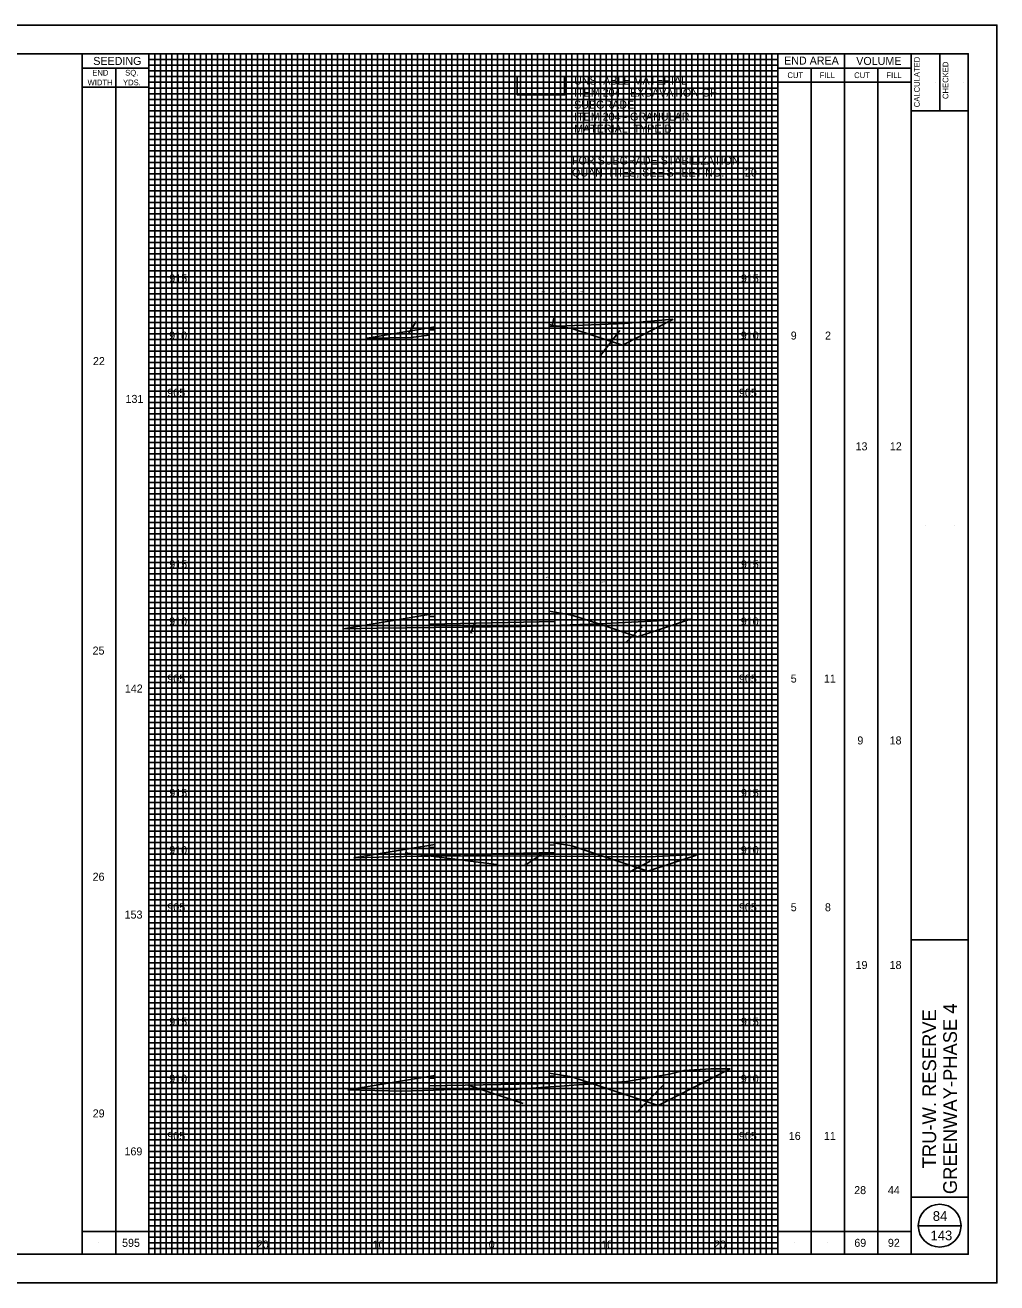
# Model space of a CAD drawing. Extents: x -73 to 160, y -2 to 1877.
# Drawn here: x 75 to 160, y 1147.5 to 1257.5 of the extents above; entities that cross this region are included whole.
import ezdxf

# ---------------------------------------------------------------- set-up
doc = ezdxf.new("R2010")
doc.units = 0
for name, color, linetype in [('DR_P_Flood_Boundary', 7, 'Continuous'), ('GK_Cells', 7, 'Continuous'), ('PV_P_EOP', 7, 'Continuous'), ('RD_X_Fence', 7, 'Continuous'), ('TX_X_5', 7, 'Continuous'), ('UT_P_Water_Cells', 7, 'Continuous'), ('XS_P_Pavt_Layers', 7, 'Continuous'), ('XS_P_Pavt_Surface', 7, 'Continuous'), ('XS_P_Special_Benching', 7, 'Continuous'), ('XS_X_Ground_Line', 7, 'Continuous')]:
    doc.layers.add(name, color=color, linetype=linetype)

msp = doc.modelspace()

# ---------------------------------------------------------------- linework, layer by layer
at = {"layer": 'DR_P_Flood_Boundary'}
for p, q in [((90.83, 1150), (90.83, 1255)), ((95.83, 1150), (95.83, 1255)), ((100.83, 1150), (100.83, 1255)), ((105.83, 1150), (105.83, 1255)), ((110.83, 1150), (110.83, 1255)), ((115.83, 1150), (115.83, 1255)), ((120.83, 1150), (120.83, 1255)), ((125.83, 1150), (125.83, 1255)), ((130.83, 1150), (130.83, 1255)), ((135.83, 1150), (135.83, 1255)), ((85.83, 1250), (140.83, 1250)), ((85.83, 1245), (140.83, 1245)), ((85.83, 1240), (140.83, 1240)), ((85.83, 1235), (140.83, 1235)), ((85.83, 1230), (140.83, 1230)), ((85.83, 1225), (140.83, 1225)), ((85.83, 1220), (140.83, 1220)), ((85.83, 1215), (140.83, 1215)), ((85.83, 1210), (140.83, 1210)), ((85.83, 1205), (140.83, 1205)), ((85.83, 1200), (140.83, 1200)), ((85.83, 1195), (140.83, 1195)), ((85.83, 1190), (140.83, 1190)), ((85.83, 1185), (140.83, 1185)), ((85.83, 1180), (140.83, 1180)), ((85.83, 1175), (140.83, 1175)), ((85.83, 1170), (140.83, 1170)), ((85.83, 1165), (140.83, 1165)), ((85.83, 1160), (140.83, 1160)), ((85.83, 1155), (140.83, 1155))]:
    msp.add_line(p, q, dxfattribs=at)
at = {"layer": 'GK_Cells'}
for p, q in [((152.5, 1150), (152.5, 1255)), ((155, 1255), (155, 1250)), ((152.5, 1250), (157.5, 1250)), ((152.5, 1177.5), (157.5, 1177.5)), ((152.5, 1155), (157.5, 1155))]:
    msp.add_line(p, q, dxfattribs=at)
msp.add_lwpolyline([(0, 1255), (157.5, 1255), (157.5, 1150), (0, 1150)], close=True, dxfattribs=at)
at = {"layer": 'PV_P_EOP'}
msp.add_lwpolyline([(118.05, 1253.02), (122.19, 1253.02), (122.19, 1251.4), (118.05, 1251.4)], close=True, dxfattribs=at)
msp.add_lwpolyline([(118.05, 1251.4), (122.19, 1251.4), (122.19, 1253.02), (118.05, 1253.02), (118.05, 1251.4)], dxfattribs=at)
at = {"layer": 'RD_X_Fence'}
for p, q in [((110.83, 1231.11), (104.92, 1230.12)), ((108.54, 1230.49), (109.21, 1231.59)), ((120.83, 1231.31), (120.83, 1231.2)), ((121.6, 1231.18), (120.83, 1231.31)), ((120.83, 1231.15), (121.6, 1231.18)), ((121.09, 1231.21), (121.25, 1231.86)), ((121.6, 1231.18), (122.83, 1230.97)), ((122.83, 1230.97), (127.25, 1229.5)), ((127.25, 1229.5), (131.67, 1231.75)), ((110.33, 1230.85), (110.83, 1230.86)), ((110.33, 1230.4), (110.33, 1230.85)), ((127.01, 1230.79), (125.34, 1228.6)), ((110.83, 1206.04), (102.84, 1204.71)), ((110.33, 1205.78), (110.83, 1205.79)), ((110.33, 1205.12), (110.33, 1205.78)), ((122.83, 1205.91), (120.83, 1206.24)), ((120.83, 1205.99), (121.33, 1206)), ((121.33, 1206), (121.33, 1205.34)), ((125.18, 1205.13), (122.83, 1205.91)), ((121.33, 1205.34), (110.33, 1205.12)), ((114.3, 1205.21), (113.98, 1204.33)), ((133.19, 1205.54), (125.18, 1205.13)), ((125.18, 1205.13), (128.56, 1204)), ((128.98, 1204.89), (127.6, 1203.55)), ((128.56, 1204), (133.19, 1205.54)), ((110.83, 1185.84), (103.76, 1184.67)), ((122.83, 1185.71), (120.83, 1186.04)), ((120.83, 1185.79), (121.33, 1185.8)), ((121.33, 1185.8), (121.33, 1185.14)), ((108.25, 1185.11), (116.23, 1184.09)), ((110.33, 1185.58), (110.83, 1185.59)), ((110.33, 1184.92), (110.33, 1185.58)), ((121.33, 1185.14), (110.33, 1184.92)), ((120.36, 1185.12), (118.83, 1184.08)), ((125.62, 1184.78), (122.83, 1185.71)), ((125.62, 1184.78), (129.46, 1183.5)), ((129.46, 1183.5), (133.72, 1184.92)), ((129.66, 1184.38), (127.83, 1183.43)), ((130.36, 1163), (136.68, 1166.22)), ((110.83, 1165.64), (103.24, 1164.38)), ((110.33, 1165.38), (110.83, 1165.39)), ((110.33, 1164.72), (110.33, 1165.38)), ((121.33, 1164.94), (110.33, 1164.72)), ((122.83, 1165.51), (120.83, 1165.84)), ((120.83, 1165.59), (121.33, 1165.6)), ((121.33, 1165.6), (121.33, 1164.94)), ((124.67, 1164.9), (122.83, 1165.51)), ((113.74, 1164.78), (118.57, 1163.2)), ((124.67, 1164.9), (130.36, 1163)), ((130.82, 1164.78), (128.5, 1162.42))]:
    msp.add_line(p, q, dxfattribs=at)
for points in [[(110.83, 1230.86), (110.83, 1231), (110.83, 1231.11)], [(120.83, 1231.2), (120.83, 1231.15)], [(131.66, 1231.79), (127.46, 1231.4), (121.6, 1231.18)], [(131.67, 1231.75), (131.66, 1231.79)], [(104.92, 1230.12), (108.74, 1230.18), (110.33, 1230.4)], [(110.83, 1205.79), (110.83, 1205.94), (110.83, 1206.04)], [(120.83, 1206.24), (120.83, 1206.14), (120.83, 1205.99)], [(102.84, 1204.71), (105.79, 1204.75), (115.83, 1204.87), (118.47, 1204.9), (125.18, 1205.13)], [(133.19, 1205.54), (133.19, 1205.54)], [(110.83, 1185.59), (110.83, 1185.74), (110.83, 1185.84)], [(120.83, 1186.04), (120.83, 1185.94), (120.83, 1185.79)], [(103.76, 1184.67), (108.13, 1184.8), (110.33, 1184.82)], [(110.33, 1184.92), (110.33, 1184.82)], [(110.33, 1184.82), (110.33, 1184.92)], [(110.33, 1184.82), (113.35, 1184.86), (115.83, 1184.84), (125.62, 1184.78)], [(133.71, 1184.97), (129.55, 1184.76), (125.62, 1184.78)], [(133.72, 1184.92), (133.71, 1184.97)], [(136.68, 1166.22), (134.97, 1166.23), (132.62, 1166.06), (131.37, 1165.76), (127.6, 1165.1), (124.67, 1164.9)], [(110.83, 1165.39), (110.83, 1165.54), (110.83, 1165.64)], [(120.83, 1165.84), (120.83, 1165.74), (120.83, 1165.59)], [(103.24, 1164.38), (107.95, 1164.26), (112.55, 1164.4), (115.83, 1164.38), (117.21, 1164.38), (124.67, 1164.9)]]:
    msp.add_lwpolyline(points, dxfattribs=at)
at = {"layer": 'TX_X_5'}
msp.add_lwpolyline([(-10, 1147.5), (160, 1147.5), (160, 1257.5), (-10, 1257.5)], close=True, dxfattribs=at)
at = {"layer": 'UT_P_Water_Cells'}
for p, q in [((85.83, 1254.5), (140.83, 1254.5)), ((85.83, 1254), (140.83, 1254)), ((86.33, 1150), (86.33, 1255)), ((86.83, 1150), (86.83, 1255)), ((87.33, 1150), (87.33, 1255)), ((87.83, 1150), (87.83, 1255)), ((88.33, 1150), (88.33, 1255)), ((88.83, 1150), (88.83, 1255)), ((89.33, 1150), (89.33, 1255)), ((89.83, 1150), (89.83, 1255)), ((90.33, 1150), (90.33, 1255)), ((91.33, 1150), (91.33, 1255)), ((91.83, 1150), (91.83, 1255)), ((92.33, 1150), (92.33, 1255)), ((92.83, 1150), (92.83, 1255)), ((93.33, 1150), (93.33, 1255)), ((93.83, 1150), (93.83, 1255)), ((94.33, 1150), (94.33, 1255)), ((94.83, 1150), (94.83, 1255)), ((95.33, 1150), (95.33, 1255)), ((96.33, 1150), (96.33, 1255)), ((96.83, 1150), (96.83, 1255)), ((97.33, 1150), (97.33, 1255)), ((97.83, 1150), (97.83, 1255)), ((98.33, 1150), (98.33, 1255)), ((98.83, 1150), (98.83, 1255)), ((99.33, 1150), (99.33, 1255)), ((99.83, 1150), (99.83, 1255)), ((100.33, 1150), (100.33, 1255)), ((101.33, 1150), (101.33, 1255)), ((101.83, 1150), (101.83, 1255)), ((102.33, 1150), (102.33, 1255)), ((102.83, 1150), (102.83, 1255)), ((103.33, 1150), (103.33, 1255)), ((103.83, 1150), (103.83, 1255)), ((104.33, 1150), (104.33, 1255)), ((104.83, 1150), (104.83, 1255)), ((105.33, 1150), (105.33, 1255)), ((106.33, 1150), (106.33, 1255)), ((106.83, 1150), (106.83, 1255)), ((107.33, 1150), (107.33, 1255)), ((107.83, 1150), (107.83, 1255)), ((108.33, 1150), (108.33, 1255)), ((108.83, 1150), (108.83, 1255)), ((109.33, 1150), (109.33, 1255)), ((109.83, 1150), (109.83, 1255)), ((110.33, 1150), (110.33, 1255)), ((111.33, 1150), (111.33, 1255)), ((111.83, 1150), (111.83, 1255)), ((112.33, 1150), (112.33, 1255)), ((112.83, 1150), (112.83, 1255)), ((113.33, 1150), (113.33, 1255)), ((113.83, 1150), (113.83, 1255)), ((114.33, 1150), (114.33, 1255)), ((114.83, 1150), (114.83, 1255)), ((115.33, 1150), (115.33, 1255)), ((116.33, 1150), (116.33, 1255)), ((116.83, 1150), (116.83, 1255)), ((117.33, 1150), (117.33, 1255)), ((117.83, 1150), (117.83, 1255)), ((118.33, 1150), (118.33, 1255)), ((118.83, 1150), (118.83, 1255)), ((119.33, 1150), (119.33, 1255)), ((119.83, 1150), (119.83, 1255)), ((120.33, 1150), (120.33, 1255)), ((121.33, 1150), (121.33, 1255)), ((121.83, 1150), (121.83, 1255)), ((122.33, 1150), (122.33, 1255)), ((122.83, 1150), (122.83, 1255)), ((123.33, 1150), (123.33, 1255)), ((123.83, 1150), (123.83, 1255)), ((124.33, 1150), (124.33, 1255)), ((124.83, 1150), (124.83, 1255)), ((125.33, 1150), (125.33, 1255)), ((126.33, 1150), (126.33, 1255)), ((126.83, 1150), (126.83, 1255)), ((127.33, 1150), (127.33, 1255)), ((127.83, 1150), (127.83, 1255)), ((128.33, 1150), (128.33, 1255)), ((128.83, 1150), (128.83, 1255)), ((129.33, 1150), (129.33, 1255)), ((129.83, 1150), (129.83, 1255)), ((130.33, 1150), (130.33, 1255)), ((131.33, 1150), (131.33, 1255)), ((131.83, 1150), (131.83, 1255)), ((132.33, 1150), (132.33, 1255)), ((132.83, 1150), (132.83, 1255)), ((133.33, 1150), (133.33, 1255)), ((133.83, 1150), (133.83, 1255)), ((134.33, 1150), (134.33, 1255)), ((134.83, 1150), (134.83, 1255)), ((135.33, 1150), (135.33, 1255)), ((136.33, 1150), (136.33, 1255)), ((136.83, 1150), (136.83, 1255)), ((137.33, 1150), (137.33, 1255)), ((137.83, 1150), (137.83, 1255)), ((138.33, 1150), (138.33, 1255)), ((138.83, 1150), (138.83, 1255)), ((139.33, 1150), (139.33, 1255)), ((139.83, 1150), (139.83, 1255)), ((140.33, 1150), (140.33, 1255)), ((85.83, 1253.5), (140.83, 1253.5)), ((85.83, 1253), (140.83, 1253)), ((85.83, 1252.5), (140.83, 1252.5)), ((85.83, 1252), (140.83, 1252)), ((85.83, 1251.5), (140.83, 1251.5)), ((85.83, 1251), (140.83, 1251)), ((85.83, 1250.5), (140.83, 1250.5)), ((85.83, 1249.5), (140.83, 1249.5)), ((85.83, 1249), (140.83, 1249)), ((85.83, 1248.5), (140.83, 1248.5)), ((85.83, 1248), (140.83, 1248)), ((85.83, 1247.5), (140.83, 1247.5)), ((85.83, 1247), (140.83, 1247)), ((85.83, 1246.5), (140.83, 1246.5)), ((85.83, 1246), (140.83, 1246)), ((85.83, 1245.5), (140.83, 1245.5)), ((85.83, 1244.5), (140.83, 1244.5)), ((85.83, 1244), (140.83, 1244)), ((85.83, 1243.5), (140.83, 1243.5)), ((85.83, 1243), (140.83, 1243)), ((85.83, 1242.5), (140.83, 1242.5)), ((85.83, 1242), (140.83, 1242)), ((85.83, 1241.5), (140.83, 1241.5)), ((85.83, 1241), (140.83, 1241)), ((85.83, 1240.5), (140.83, 1240.5)), ((85.83, 1239.5), (140.83, 1239.5)), ((85.83, 1239), (140.83, 1239)), ((85.83, 1238.5), (140.83, 1238.5)), ((85.83, 1238), (140.83, 1238)), ((85.83, 1237.5), (140.83, 1237.5)), ((85.83, 1237), (140.83, 1237)), ((85.83, 1236.5), (140.83, 1236.5)), ((85.83, 1236), (140.83, 1236)), ((85.83, 1235.5), (140.83, 1235.5)), ((85.83, 1234.5), (140.83, 1234.5)), ((85.83, 1234), (140.83, 1234)), ((85.83, 1233.5), (140.83, 1233.5)), ((85.83, 1233), (140.83, 1233)), ((85.83, 1232.5), (140.83, 1232.5)), ((85.83, 1232), (140.83, 1232)), ((85.83, 1231.5), (140.83, 1231.5)), ((85.83, 1231), (140.83, 1231)), ((85.83, 1230.5), (140.83, 1230.5)), ((85.83, 1229.5), (140.83, 1229.5)), ((85.83, 1229), (140.83, 1229)), ((85.83, 1228.5), (140.83, 1228.5)), ((85.83, 1228), (140.83, 1228)), ((85.83, 1227.5), (140.83, 1227.5)), ((85.83, 1227), (140.83, 1227)), ((85.83, 1226.5), (140.83, 1226.5)), ((85.83, 1226), (140.83, 1226)), ((85.83, 1225.5), (140.83, 1225.5)), ((85.83, 1224.5), (140.83, 1224.5)), ((85.83, 1224), (140.83, 1224)), ((85.83, 1223.5), (140.83, 1223.5)), ((85.83, 1223), (140.83, 1223)), ((85.83, 1222.5), (140.83, 1222.5)), ((85.83, 1222), (140.83, 1222)), ((85.83, 1221.5), (140.83, 1221.5)), ((85.83, 1221), (140.83, 1221)), ((85.83, 1220.5), (140.83, 1220.5)), ((85.83, 1219.5), (140.83, 1219.5)), ((85.83, 1219), (140.83, 1219)), ((85.83, 1218.5), (140.83, 1218.5)), ((85.83, 1218), (140.83, 1218)), ((85.83, 1217.5), (140.83, 1217.5)), ((85.83, 1217), (140.83, 1217)), ((85.83, 1216.5), (140.83, 1216.5)), ((85.83, 1216), (140.83, 1216)), ((85.83, 1215.5), (140.83, 1215.5)), ((85.83, 1214.5), (140.83, 1214.5)), ((85.83, 1214), (140.83, 1214)), ((85.83, 1213.5), (140.83, 1213.5)), ((85.83, 1213), (140.83, 1213)), ((85.83, 1212.5), (140.83, 1212.5)), ((85.83, 1212), (140.83, 1212)), ((85.83, 1211.5), (140.83, 1211.5)), ((85.83, 1211), (140.83, 1211)), ((85.83, 1210.5), (140.83, 1210.5)), ((85.83, 1209.5), (140.83, 1209.5)), ((85.83, 1209), (140.83, 1209)), ((85.83, 1208.5), (140.83, 1208.5)), ((85.83, 1208), (140.83, 1208)), ((85.83, 1207.5), (140.83, 1207.5)), ((85.83, 1207), (140.83, 1207)), ((85.83, 1206.5), (140.83, 1206.5)), ((85.83, 1206), (140.83, 1206)), ((85.83, 1205.5), (140.83, 1205.5)), ((85.83, 1204.5), (140.83, 1204.5)), ((85.83, 1204), (140.83, 1204)), ((85.83, 1203.5), (140.83, 1203.5)), ((85.83, 1203), (140.83, 1203)), ((85.83, 1202.5), (140.83, 1202.5)), ((85.83, 1202), (140.83, 1202)), ((85.83, 1201.5), (140.83, 1201.5)), ((85.83, 1201), (140.83, 1201)), ((85.83, 1200.5), (140.83, 1200.5)), ((85.83, 1199.5), (140.83, 1199.5)), ((85.83, 1199), (140.83, 1199)), ((85.83, 1198.5), (140.83, 1198.5)), ((85.83, 1198), (140.83, 1198)), ((85.83, 1197.5), (140.83, 1197.5)), ((85.83, 1197), (140.83, 1197)), ((85.83, 1196.5), (140.83, 1196.5)), ((85.83, 1196), (140.83, 1196)), ((85.83, 1195.5), (140.83, 1195.5)), ((85.83, 1194.5), (140.83, 1194.5)), ((85.83, 1194), (140.83, 1194)), ((85.83, 1193.5), (140.83, 1193.5)), ((85.83, 1193), (140.83, 1193)), ((85.83, 1192.5), (140.83, 1192.5)), ((85.83, 1192), (140.83, 1192)), ((85.83, 1191.5), (140.83, 1191.5)), ((85.83, 1191), (140.83, 1191)), ((85.83, 1190.5), (140.83, 1190.5)), ((85.83, 1189.5), (140.83, 1189.5)), ((85.83, 1189), (140.83, 1189)), ((85.83, 1188.5), (140.83, 1188.5)), ((85.83, 1188), (140.83, 1188)), ((85.83, 1187.5), (140.83, 1187.5)), ((85.83, 1187), (140.83, 1187)), ((85.83, 1186.5), (140.83, 1186.5)), ((85.83, 1186), (140.83, 1186)), ((85.83, 1185.5), (140.83, 1185.5)), ((85.83, 1184.5), (140.83, 1184.5)), ((85.83, 1184), (140.83, 1184)), ((85.83, 1183.5), (140.83, 1183.5)), ((85.83, 1183), (140.83, 1183)), ((85.83, 1182.5), (140.83, 1182.5)), ((85.83, 1182), (140.83, 1182)), ((85.83, 1181.5), (140.83, 1181.5)), ((85.83, 1181), (140.83, 1181)), ((85.83, 1180.5), (140.83, 1180.5)), ((85.83, 1179.5), (140.83, 1179.5)), ((85.83, 1179), (140.83, 1179)), ((85.83, 1178.5), (140.83, 1178.5)), ((85.83, 1178), (140.83, 1178)), ((85.83, 1177.5), (140.83, 1177.5)), ((85.83, 1177), (140.83, 1177)), ((85.83, 1176.5), (140.83, 1176.5)), ((85.83, 1176), (140.83, 1176)), ((85.83, 1175.5), (140.83, 1175.5)), ((85.83, 1174.5), (140.83, 1174.5)), ((85.83, 1174), (140.83, 1174)), ((85.83, 1173.5), (140.83, 1173.5)), ((85.83, 1173), (140.83, 1173)), ((85.83, 1172.5), (140.83, 1172.5)), ((85.83, 1172), (140.83, 1172)), ((85.83, 1171.5), (140.83, 1171.5)), ((85.83, 1171), (140.83, 1171)), ((85.83, 1170.5), (140.83, 1170.5)), ((85.83, 1169.5), (140.83, 1169.5)), ((85.83, 1169), (140.83, 1169)), ((85.83, 1168.5), (140.83, 1168.5)), ((85.83, 1168), (140.83, 1168)), ((85.83, 1167.5), (140.83, 1167.5)), ((85.83, 1167), (140.83, 1167)), ((85.83, 1166.5), (140.83, 1166.5)), ((85.83, 1166), (140.83, 1166)), ((85.83, 1165.5), (140.83, 1165.5)), ((85.83, 1164.5), (140.83, 1164.5)), ((85.83, 1164), (140.83, 1164)), ((85.83, 1163.5), (140.83, 1163.5)), ((85.83, 1163), (140.83, 1163)), ((85.83, 1162.5), (140.83, 1162.5)), ((85.83, 1162), (140.83, 1162)), ((85.83, 1161.5), (140.83, 1161.5)), ((85.83, 1161), (140.83, 1161)), ((85.83, 1160.5), (140.83, 1160.5)), ((85.83, 1159.5), (140.83, 1159.5)), ((85.83, 1159), (140.83, 1159)), ((85.83, 1158.5), (140.83, 1158.5)), ((85.83, 1158), (140.83, 1158)), ((85.83, 1157.5), (140.83, 1157.5)), ((85.83, 1157), (140.83, 1157)), ((85.83, 1156.5), (140.83, 1156.5)), ((85.83, 1156), (140.83, 1156)), ((85.83, 1155.5), (140.83, 1155.5)), ((85.83, 1154.5), (140.83, 1154.5)), ((85.83, 1154), (140.83, 1154)), ((85.83, 1153.5), (140.83, 1153.5)), ((85.83, 1153), (140.83, 1153)), ((85.83, 1152.5), (140.83, 1152.5)), ((85.83, 1152), (140.83, 1152)), ((85.83, 1151.5), (140.83, 1151.5)), ((85.83, 1151), (140.83, 1151)), ((85.83, 1150.5), (140.83, 1150.5))]:
    msp.add_line(p, q, dxfattribs=at)
at = {"layer": 'XS_X_Ground_Line'}
for p, q in [((80, 1150), (80, 1255)), ((85.83, 1150), (85.83, 1255)), ((140.83, 1150), (140.83, 1255)), ((146.67, 1150), (146.67, 1255)), ((85.83, 1253.75), (80, 1253.75)), ((82.92, 1150), (82.92, 1253.75)), ((140.83, 1253.75), (152.5, 1253.75)), ((143.75, 1150), (143.75, 1253.75)), ((149.58, 1150), (149.58, 1253.75)), ((85.83, 1252.08), (80, 1252.08)), ((140.83, 1252.5), (152.5, 1252.5)), ((154.6, 1252.52), (154.6, 1252.52)), ((157.1, 1252.52), (157.1, 1252.52)), ((153.75, 1213.75), (153.75, 1213.75)), ((156.26, 1213.75), (156.26, 1213.75)), ((155, 1166.46), (155, 1166.46)), ((155, 1152.92), (155, 1152.92)), ((80, 1152), (85.83, 1152)), ((140.83, 1152), (152.5, 1152)), ((153.12, 1152.5), (156.88, 1152.5)), ((81.46, 1151.03), (81.46, 1151.03)), ((84.37, 1151.03), (84.37, 1151.03)), ((142.29, 1151), (142.29, 1151)), ((145.21, 1151), (145.21, 1151)), ((148.12, 1151), (148.12, 1151)), ((151.04, 1151), (151.04, 1151)), ((155, 1151.22), (155, 1151.22))]:
    msp.add_line(p, q, dxfattribs=at)
msp.add_circle((155, 1152.5), 1.87, dxfattribs=at)

# ---------------------------------------------------------------- texts
at = {"layer": 'RD_X_Fence'}
for s, p in [('11.9', (104.05, 1248.93)), ('6.0', (109.34, 1234.41)), ('2.0', (120.18, 1234.1)), ('5.0', (123.51, 1234.12)), ('4.7', (121.99, 1234.05)), ('2.2', (109.07, 1231.52)), ('0.1', (121.13, 1231.79)), ('9.2', (125.2, 1228.53)), ('8.1', (107.56, 1208.9)), ('2.0', (120.54, 1209.16)), ('6.0', (123.38, 1208.68)), ('4.9', (125.44, 1208.74)), ('10.8', (113.79, 1204.26)), ('5.2', (127.46, 1203.48)), ('7.2', (108, 1188.45)), ('2.0', (120.16, 1188.09)), ('7.0', (121.99, 1188.22)), ('5.2', (123.88, 1188.2)), ('3.1', (116.11, 1184.02)), ('5.0', (118.68, 1184.01)), ('5.2', (127.69, 1183.36)), ('7.7', (107.97, 1168.65)), ('2.0', (121.12, 1168.65)), ('7.9', (124.35, 1168.52)), ('7.1', (126.37, 1168.55)), ('11.3', (118.42, 1163.13)), ('16.0', (128.31, 1162.35))]:
    msp.add_text(s, height=0.14, dxfattribs=at).set_placement(p)
at = {"layer": 'XS_P_Pavt_Layers'}
for s, p in [('84', (154.4, 1152.92)), ('143', (154.2, 1151.22))]:
    msp.add_text(s, height=0.85, dxfattribs=at).set_placement(p)
at = {"layer": 'XS_P_Pavt_Surface'}
for s, p in [('915', (87.61, 1235)), ('915', (137.61, 1235)), ('910', (87.6, 1230)), ('910', (137.6, 1230)), ('9', (141.97, 1230)), ('2', (144.97, 1230)), ('22', (80.93, 1227.77)), ('905', (87.44, 1225)), ('905', (137.44, 1225)), ('131', (83.78, 1224.46)), ('13', (147.64, 1220.31)), ('12', (150.64, 1220.31)), ('915', (87.61, 1210)), ('915', (137.61, 1210)), ('910', (87.6, 1205)), ('910', (137.6, 1205)), ('25', (80.9, 1202.45)), ('905', (87.44, 1200)), ('905', (137.44, 1200)), ('5', (141.97, 1200)), ('11', (144.87, 1200)), ('142', (83.72, 1199.13)), ('9', (147.8, 1194.59)), ('18', (150.62, 1194.59)), ('915', (87.61, 1190)), ('915', (137.61, 1190)), ('910', (87.6, 1185)), ('910', (137.6, 1185)), ('26', (80.9, 1182.67)), ('905', (87.44, 1180)), ('905', (137.44, 1180)), ('5', (141.97, 1180)), ('8', (144.96, 1180)), ('153', (83.7, 1179.36)), ('19', (147.64, 1174.95)), ('18', (150.62, 1174.95)), ('915', (87.61, 1170)), ('915', (137.61, 1170)), ('910', (87.6, 1165)), ('910', (137.6, 1165)), ('29', (80.91, 1161.97)), ('905', (87.44, 1160)), ('905', (137.44, 1160)), ('16', (141.8, 1160)), ('11', (144.87, 1160)), ('169', (83.69, 1158.65)), ('28', (147.52, 1155.26)), ('44', (150.47, 1155.26)), ('595', (83.48, 1150.65)), ('20', (95.26, 1150.5)), ('10', (105.39, 1150.5)), ('0', (115.55, 1150.5)), ('0', (115.55, 1150.5)), ('10', (125.39, 1150.5)), ('20', (135.26, 1150.5)), ('69', (147.53, 1150.65)), ('92', (150.47, 1150.65))]:
    msp.add_text(s, height=0.7, dxfattribs=at).set_placement(p)
for s, p in [('GREENWAY-PHASE 4', (156.51, 1155.26)), ('TRU-W. RESERVE', (154.69, 1157.52))]:
    msp.add_text(s, height=1.2, rotation=90, dxfattribs=at).set_placement(p)
at = {"layer": 'XS_P_Special_Benching'}
for s, p in [('UNSTABLE MATERIAL', (123.02, 1252.3)), ('ITEM 204 - EXCAVATION OF', (123.02, 1251.25)), ('SUBGRADE', (123.02, 1250.2)), ('ITEM 204 - GRANULAR', (123.02, 1249.15)), ('MATERIAL, TYPE B', (123.02, 1248.1)), ('FOR SUBGRADE STABILIZATION', (122.84, 1245.31)), ('QUANTITIES, SEE SHEET NO.', (122.84, 1244.26)), ('20', (137.96, 1244.26))]:
    msp.add_text(s, height=0.7, dxfattribs=at).set_placement(p)
at = {"layer": 'XS_X_Ground_Line'}
for s, height, p in [('SEEDING', 0.7, (80.96, 1254.02)), ('END AREA', 0.7, (141.39, 1254.05)), ('VOLUME', 0.7, (147.7, 1254.02)), ('END', 0.5, (80.87, 1253.09)), ('SQ.', 0.5, (83.75, 1253.09)), ('CUT', 0.5, (141.68, 1252.87)), ('FILL', 0.5, (144.5, 1252.87)), ('CUT', 0.5, (147.52, 1252.87)), ('FILL', 0.5, (150.34, 1252.87)), ('WIDTH', 0.5, (80.46, 1252.24)), ('YDS.', 0.5, (83.56, 1252.24)), ('143', 0.85, (154.2, 1151.22))]:
    msp.add_text(s, height=height, dxfattribs=at).set_placement(p)
for s, p in [('CALCULATED', (153.26, 1250.32)), ('CHECKED', (155.76, 1251.04))]:
    msp.add_text(s, height=0.5, rotation=90, dxfattribs=at).set_placement(p)

doc.saveas('drawing.dxf')
